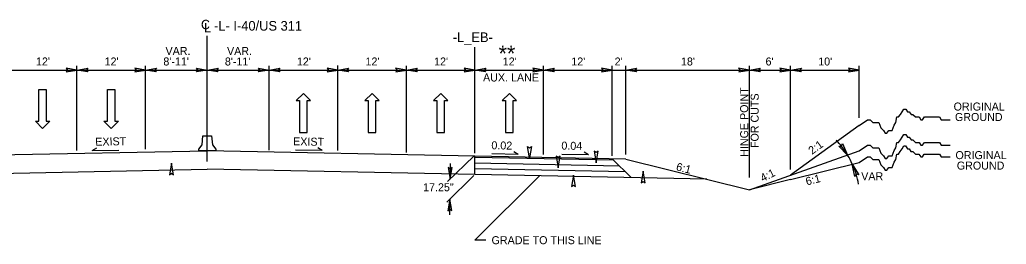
# Model space of a CAD drawing. Extents: x 1726582 to 1728895, y 538986 to 541550.
# Drawn here: x 1727397 to 1728260, y 540347 to 540544 of the extents above; entities that cross this region are included whole.
import ezdxf

# ---------------------------------------------------------------- set-up
doc = ezdxf.new("R2010")
doc.units = 0
for name, color, linetype in [('Default', 7, 'Continuous'), ('GSExisting', 7, 'Continuous'), ('GSProposed', 7, 'Continuous'), ('GSRelocate', 7, 'Continuous'), ('GSRemove', 7, 'Continuous'), ('GSReplace', 7, 'Continuous'), ('Typical Terminator CELL', 7, 'Continuous'), ('Typical Text General CELL', 7, 'Continuous')]:
    doc.layers.add(name, color=color, linetype=linetype)

msp = doc.modelspace()

# ---------------------------------------------------------------- linework, layer by layer
at = {"layer": 'Default'}
for p, q in [((1727795.33, 540427.18), (1727795.33, 540520.09)), ((1727447.04, 540429.59), (1727447.04, 540503.77)), ((1727507.09, 540430.79), (1727507.09, 540503.77)), ((1727615.18, 540429.8), (1727615.18, 540503.77)), ((1727675.34, 540429.58), (1727675.34, 540503.92)), ((1727735.39, 540427.79), (1727735.39, 540503.89)), ((1727795.33, 540427.18), (1727795.33, 540503.89)), ((1727855.37, 540425.98), (1727855.37, 540503.77)), ((1727915.42, 540425.98), (1727915.42, 540503.77)), ((1727915.42, 540424.78), (1727915.42, 540503.77)), ((1727927.43, 540425.98), (1727927.43, 540503.77)), ((1728035.55, 540405.77), (1728035.55, 540503.77)), ((1728071.58, 540412.81), (1728071.58, 540503.77)), ((1728131.63, 540458.2), (1728131.63, 540503.77)), ((1727386.99, 540500.07), (1727447.04, 540500.07)), ((1727447.04, 540500.07), (1727507.09, 540500.07)), ((1727507.09, 540500.07), (1727561.09, 540500.07)), ((1727561.09, 540500.07), (1727615.29, 540500.07)), ((1727615.29, 540500.07), (1727675.34, 540500.07)), ((1727675.34, 540500.07), (1727735.39, 540500.07)), ((1727735.39, 540500.07), (1727795.43, 540500.07)), ((1727795.43, 540500.07), (1727855.48, 540500.07)), ((1727855.48, 540500.07), (1727915.53, 540500.07)), ((1727855.48, 540500.07), (1727915.53, 540500.07)), ((1727915.53, 540500.07), (1727927.43, 540500.07)), ((1727927.43, 540500.07), (1728035.51, 540500.07)), ((1728035.51, 540500.07), (1728071.54, 540500.07)), ((1728071.54, 540500.07), (1728131.59, 540500.07)), ((1727413.62, 540455.17), (1727413.62, 540483.17)), ((1727413.62, 540483.17), (1727420.22, 540483.17)), ((1727420.22, 540483.17), (1727420.22, 540455.17)), ((1727473.66, 540455.17), (1727473.66, 540483.17)), ((1727473.66, 540483.17), (1727480.26, 540483.17)), ((1727480.26, 540483.17), (1727480.26, 540455.17)), ((1727645.32, 540479.59), (1727638.92, 540473.29)), ((1727651.52, 540473.29), (1727645.32, 540479.59)), ((1727705.36, 540479.59), (1727698.96, 540473.29)), ((1727711.56, 540473.29), (1727705.36, 540479.59)), ((1727765.41, 540479.59), (1727759.01, 540473.29)), ((1727771.61, 540473.29), (1727765.41, 540479.59)), ((1727825.46, 540479.59), (1727819.06, 540473.29)), ((1727831.66, 540473.29), (1727825.46, 540479.59)), ((1727638.92, 540473.29), (1727641.92, 540473.29)), ((1727641.92, 540473.29), (1727641.92, 540445.29)), ((1727648.52, 540445.29), (1727648.52, 540473.29)), ((1727648.52, 540473.29), (1727651.52, 540473.29)), ((1727698.96, 540473.29), (1727701.96, 540473.29)), ((1727701.96, 540473.29), (1727701.96, 540445.29)), ((1727708.56, 540445.29), (1727708.56, 540473.29)), ((1727708.56, 540473.29), (1727711.56, 540473.29)), ((1727759.01, 540473.29), (1727762.01, 540473.29)), ((1727762.01, 540473.29), (1727762.01, 540445.29)), ((1727768.61, 540445.29), (1727768.61, 540473.29)), ((1727768.61, 540473.29), (1727771.61, 540473.29)), ((1727819.06, 540473.29), (1727822.06, 540473.29)), ((1727822.06, 540473.29), (1727822.06, 540445.29)), ((1727828.66, 540445.29), (1727828.66, 540473.29)), ((1727828.66, 540473.29), (1727831.66, 540473.29)), ((1727417.02, 540448.87), (1727410.62, 540455.17)), ((1727410.62, 540455.17), (1727413.62, 540455.17)), ((1727423.22, 540455.17), (1727417.02, 540448.87)), ((1727420.22, 540455.17), (1727423.22, 540455.17)), ((1727477.06, 540448.87), (1727470.66, 540455.17)), ((1727470.66, 540455.17), (1727473.66, 540455.17)), ((1727483.26, 540455.17), (1727477.06, 540448.87)), ((1727480.26, 540455.17), (1727483.26, 540455.17)), ((1727641.92, 540445.29), (1727648.52, 540445.29)), ((1727701.96, 540445.29), (1727708.56, 540445.29)), ((1727762.01, 540445.29), (1727768.61, 540445.29)), ((1727822.06, 540445.29), (1727828.66, 540445.29)), ((1727794.5, 540424.56), (1727771.21, 540402.26)), ((1727773.55, 540418.26), (1727773.55, 540404.5)), ((1727794.5, 540407.67), (1727770.67, 540384.19)), ((1727773.43, 540373.15), (1727773.43, 540386.91))]:
    msp.add_line(p, q, dxfattribs=at)
for points in [[(1727437.66, 540498.46), (1727447.04, 540500.07), (1727437.61, 540501.74), (1727438.81, 540500.07)], [(1727456.42, 540498.46), (1727447.04, 540500.07), (1727456.47, 540501.74), (1727455.27, 540500.07)], [(1727497.71, 540498.46), (1727507.09, 540500.07), (1727497.66, 540501.74), (1727498.85, 540500.07)], [(1727516.47, 540498.46), (1727507.09, 540500.07), (1727516.52, 540501.74), (1727515.32, 540500.07)], [(1727551.71, 540501.69), (1727561.09, 540500.07), (1727551.66, 540498.41), (1727552.85, 540500.07)], [(1727570.46, 540498.45), (1727561.09, 540500.07), (1727570.52, 540501.74), (1727569.32, 540500.07)], [(1727605.81, 540501.69), (1727615.18, 540500.07), (1727605.75, 540498.4), (1727606.95, 540500.07)], [(1727624.56, 540498.45), (1727615.18, 540500.07), (1727624.61, 540501.74), (1727623.42, 540500.07)], [(1727665.96, 540498.45), (1727675.34, 540500.07), (1727665.91, 540501.74), (1727667.11, 540500.07)], [(1727684.72, 540498.45), (1727675.34, 540500.07), (1727684.77, 540501.74), (1727683.57, 540500.07)], [(1727726.01, 540498.45), (1727735.39, 540500.07), (1727725.96, 540501.74), (1727727.16, 540500.07)], [(1727744.77, 540498.45), (1727735.39, 540500.07), (1727744.82, 540501.74), (1727743.62, 540500.07)], [(1727785.95, 540498.45), (1727795.33, 540500.07), (1727785.9, 540501.74), (1727787.09, 540500.07)], [(1727804.7, 540498.45), (1727795.33, 540500.07), (1727804.76, 540501.74), (1727803.56, 540500.07)], [(1727845.99, 540498.45), (1727855.37, 540500.07), (1727845.94, 540501.74), (1727847.14, 540500.07)], [(1727864.75, 540498.45), (1727855.37, 540500.07), (1727864.8, 540501.74), (1727863.6, 540500.07)], [(1727906.04, 540498.45), (1727915.42, 540500.07), (1727905.99, 540501.74), (1727907.19, 540500.07)], [(1727936.81, 540498.45), (1727927.43, 540500.07), (1727936.86, 540501.74), (1727935.66, 540500.07)], [(1728026.17, 540498.46), (1728035.55, 540500.08), (1728026.12, 540501.74), (1728027.32, 540500.08)], [(1728044.93, 540498.46), (1728035.55, 540500.08), (1728044.98, 540501.74), (1728043.78, 540500.08)], [(1728062.2, 540498.46), (1728071.58, 540500.08), (1728062.15, 540501.74), (1728063.35, 540500.08)], [(1728080.96, 540498.46), (1728071.58, 540500.08), (1728081.01, 540501.74), (1728079.81, 540500.08)], [(1728122.21, 540498.45), (1728131.59, 540500.07), (1728122.16, 540501.74), (1728123.36, 540500.07)], [(1728116.91, 540435.57), (1728121.46, 540425.59), (1728113.75, 540433.49), (1728116.12, 540433.43)], [(1728127.83, 540406.84), (1728125.5, 540417.56), (1728131.36, 540408.2), (1728129.06, 540408.76)], [(1728127.83, 540406.84), (1728125.5, 540417.56), (1728131.36, 540408.2), (1728129.06, 540408.76)]]:
    msp.add_lwpolyline(points, close=True, dxfattribs=at)
at = {"layer": 'GSExisting'}
for points in [[(1728131.59, 540451.51), (1728138.81, 540456.57), (1728141.15, 540456.57), (1728143.48, 540454.24), (1728145.04, 540454.24), (1728147.38, 540454.24), (1728148.93, 540454.24), (1728150.49, 540449.55), (1728152.83, 540447.23), (1728154.39, 540444.88), (1728155.94, 540444.88), (1728157.5, 540447.23), (1728159.06, 540447.23), (1728160.61, 540447.23), (1728162.17, 540451.9), (1728163.73, 540454.24), (1728164.51, 540458.92), (1728166.07, 540458.92), (1728167.63, 540461.24), (1728169.18, 540463.59), (1728170.74, 540465.93), (1728172.3, 540465.93), (1728173.85, 540463.59), (1728175.41, 540463.59), (1728176.97, 540461.24), (1728178.53, 540461.24), (1728180.87, 540458.92), (1728182.42, 540458.92), (1728183.98, 540458.92), (1728185.54, 540456.57), (1728187.09, 540456.57), (1728188.65, 540458.92), (1728190.21, 540458.92), (1728191.77, 540458.92), (1728193.32, 540458.92), (1728194.88, 540458.92), (1728197.22, 540458.92), (1728199.55, 540458.92), (1728201.89, 540458.92), (1728203.45, 540456.57), (1728205.78, 540456.57), (1728208.12, 540456.57), (1728211.23, 540456.57)], [(1728131.59, 540429.19), (1728138.81, 540434.26), (1728141.15, 540434.26), (1728143.48, 540431.93), (1728145.04, 540431.93), (1728147.38, 540431.93), (1728148.93, 540431.93), (1728150.49, 540427.24), (1728152.83, 540424.92), (1728154.39, 540422.57), (1728155.94, 540422.57), (1728157.5, 540424.92), (1728159.06, 540424.92), (1728160.61, 540424.92), (1728162.17, 540429.59), (1728163.73, 540431.93), (1728164.51, 540436.6), (1728166.07, 540436.6), (1728167.63, 540438.93), (1728169.18, 540441.28), (1728170.74, 540443.62), (1728172.3, 540443.62), (1728173.85, 540441.28), (1728175.41, 540441.28), (1728176.97, 540438.93), (1728178.53, 540438.93), (1728180.87, 540436.6), (1728182.42, 540436.6), (1728183.98, 540436.6), (1728185.54, 540434.26), (1728187.09, 540434.26), (1728188.65, 540436.6), (1728190.21, 540436.6), (1728191.77, 540436.6), (1728193.32, 540436.6), (1728194.88, 540436.6), (1728197.22, 540436.6), (1728199.55, 540436.6), (1728201.89, 540436.6), (1728203.45, 540434.26), (1728205.78, 540434.26), (1728208.12, 540434.26), (1728211.23, 540434.26)], [(1728131.56, 540419.07), (1728138.77, 540424.14), (1728141.11, 540424.14), (1728143.45, 540421.81), (1728145, 540421.81), (1728147.34, 540421.81), (1728148.9, 540421.81), (1728150.46, 540417.12), (1728152.8, 540414.79), (1728154.35, 540412.45), (1728155.91, 540412.45), (1728157.47, 540414.79), (1728159.03, 540414.79), (1728160.58, 540414.79), (1728162.14, 540419.46), (1728163.7, 540421.81), (1728164.48, 540426.48), (1728166.04, 540426.48), (1728167.59, 540428.81), (1728169.15, 540431.15), (1728170.71, 540433.5), (1728172.26, 540433.5), (1728173.82, 540431.15), (1728175.38, 540431.15), (1728176.94, 540428.81), (1728178.49, 540428.81), (1728180.83, 540426.48), (1728182.39, 540426.48), (1728183.95, 540426.48), (1728185.5, 540424.14), (1728187.06, 540424.14), (1728188.62, 540426.48), (1728190.18, 540426.48), (1728191.73, 540426.48), (1728193.29, 540426.48), (1728194.85, 540426.48), (1728197.19, 540426.48), (1728199.52, 540426.48), (1728201.86, 540426.48), (1728203.42, 540424.14), (1728205.75, 540424.14), (1728208.09, 540424.14), (1728211.2, 540424.14)]]:
    msp.add_lwpolyline(points, dxfattribs=at)
for centre, start, end in [((1728069.06, 540395.64), 29.75191, 45.50364), ((1728071.52, 540390.56), 8.9538, 26.57006), ((1728071.52, 540390.56), 8.9538, 26.57006)]:
    msp.add_arc(centre, 60.35, start, end, dxfattribs=at)
msp.add_ellipse((1728070.97, 540428.62), major_axis=(54.47, -25.99), ratio=0.5, start_param=0.463735, end_param=0.681536, dxfattribs=at)
at = {"layer": 'GSProposed'}
for p, q in [((1727460.45, 540429.46), (1727464.36, 540431.83)), ((1727460.45, 540429.46), (1727483.76, 540429.93)), ((1727661.73, 540429.46), (1727638.41, 540429.93)), ((1727661.73, 540429.46), (1727657.81, 540431.83)), ((1727833.3, 540426.03), (1727809.99, 540426.5)), ((1727833.3, 540426.03), (1727829.38, 540428.4)), ((1727894.75, 540425.72), (1727871.44, 540426.19)), ((1727894.75, 540425.72), (1727890.84, 540428.09))]:
    msp.add_line(p, q, dxfattribs=at)
at = {"layer": 'GSRemove'}
msp.add_line((1727561.09, 540419.94), (1727561.09, 540530.03), dxfattribs=at)
at = {"layer": 'GSReplace'}
for p, q in [((1728131.59, 540451.51), (1728071.62, 540407.89)), ((1727553.59, 540430.63), (1727556.5, 540434.5)), ((1727556.5, 540434.5), (1727557.33, 540442.42)), ((1727557.33, 540442.42), (1727561.09, 540442.42)), ((1727561.09, 540442.42), (1727564.84, 540442.42)), ((1727564.84, 540442.42), (1727565.67, 540434.5)), ((1727565.67, 540434.5), (1727568.58, 540430.63)), ((1727326.84, 540424.71), (1727561.06, 540429.4)), ((1727553.59, 540429.38), (1727553.59, 540430.63)), ((1727568.58, 540429.38), (1727553.59, 540429.38)), ((1727795.33, 540424.71), (1727561.09, 540429.4)), ((1727568.58, 540430.63), (1727568.58, 540429.38)), ((1728035.5, 540395.05), (1728131.59, 540429.19)), ((1727795.33, 540408.45), (1727795.33, 540424.71)), ((1727927.44, 540422.07), (1727795.33, 540424.71)), ((1727916.7, 540421.05), (1727795.33, 540423.48)), ((1727921.83, 540415.93), (1727795.33, 540418.46)), ((1727915.42, 540422.33), (1727932.01, 540405.74)), ((1727927.44, 540422.07), (1728035.51, 540395.05)), ((1728071.52, 540404.06), (1728131.56, 540419.07)), ((1727326.84, 540408.45), (1727561.09, 540413.13)), ((1727795.33, 540408.45), (1727561.09, 540413.13)), ((1727926.93, 540410.82), (1727795.33, 540413.45)), ((1727998.15, 540404.39), (1727795.33, 540408.45)), ((1728071.52, 540404.06), (1728035.5, 540395.05))]:
    msp.add_line(p, q, dxfattribs=at)
at = {"layer": 'Typical Terminator CELL'}
for p, q in [((1727795.32, 540350.93), (1727851.78, 540407.32)), ((1727804.88, 540350.93), (1727795.32, 540350.93))]:
    msp.add_line(p, q, dxfattribs=at)
for points in [[(1727844.91, 540433.1), (1727843.18, 540423.05), (1727841.39, 540433.15), (1727843.18, 540431.87)], [(1727899.78, 540428.89), (1727901.51, 540418.85), (1727903.29, 540428.95), (1727901.51, 540427.66)], [(1727531.5, 540408.34), (1727529.77, 540418.38), (1727527.98, 540408.28), (1727529.77, 540409.56)], [(1727866.52, 540424.5), (1727868.25, 540414.46), (1727870.03, 540424.56), (1727868.25, 540423.28)], [(1727771.82, 540414.55), (1727773.55, 540404.5), (1727775.33, 540414.61), (1727773.55, 540413.32)], [(1727883.38, 540397.96), (1727881.65, 540408.01), (1727879.86, 540397.91), (1727881.65, 540399.19)], [(1727944.38, 540401.3), (1727942.65, 540411.34), (1727940.86, 540401.24), (1727942.65, 540402.52)], [(1727775.16, 540376.86), (1727773.43, 540386.91), (1727771.64, 540376.81), (1727773.43, 540378.09)]]:
    msp.add_lwpolyline(points, close=True, dxfattribs=at)

# ---------------------------------------------------------------- texts
at = {"layer": 'Default'}
msp.add_text('17.25"', height=7.005, rotation=360, dxfattribs=at).set_placement((1727749.98, 540393.86))
at = {"layer": 'GSProposed'}
for s, height, p in [('VAR.', 7.005, (1727524.54, 540513.26)), ('VAR.', 7.005, (1727578.37, 540513.26)), ('**', 14.011, (1727816.07, 540507.58)), ("12'", 7.005, (1727411.2, 540504.08)), ("12'", 7.005, (1727471.25, 540504.08)), ("8'-11'", 7.005, (1727522.66, 540504.08)), ("8'-11'", 7.005, (1727576.49, 540504.07)), ("12'", 7.005, (1727639.5, 540504.07)), ("12'", 7.005, (1727699.55, 540504.07)), ("12'", 7.005, (1727759.6, 540504.07)), ("12'", 7.005, (1727819.65, 540504.07)), ("12'", 7.005, (1727879.69, 540504.07)), ("2'", 7.005, (1727917.6, 540504.07)), ('AUX. LANE', 7.005, (1727802.43, 540490.06))]:
    msp.add_text(s, height=height, dxfattribs=at).set_placement(p)
for s, rotation, p in [('EXIST', 1.14574, (1727463.13, 540433.69)), ('EXIST', 358.85426, (1727636.19, 540434.15)), ('0.02', 358.85426, (1727809.67, 540430.68)), ('0.04', 358.85426, (1727870.93, 540430.38))]:
    msp.add_text(s, height=7.005, rotation=rotation, dxfattribs=at).set_placement(p)
at = {"layer": 'GSRelocate'}
for s, p in [("18'", (1727975.66, 540504.07)), ("6'", (1728049.65, 540504.07)), ("10'", (1728095.75, 540504.07)), ('ORIGINAL', (1728214.25, 540464.59)), ('GROUND', (1728215.43, 540455.41)), ('ORIGINAL', (1728215.87, 540422)), ('GROUND', (1728217.05, 540412.82)), ('VAR', (1728133.39, 540403.45))]:
    msp.add_text(s, height=7.005, dxfattribs=at).set_placement(p)
for s, height, rotation, p in [('HINGE POINT', 7.0055, 90, (1728034.46, 540424.05)), ('FOR CUTS', 7.005, 90, (1728043.65, 540431.72)), ('2:1', 7.005, 36.02984, (1728090.3, 540425.68)), ('6:1', 7.005, 345.96376, (1727970.91, 540412.26)), ('4:1', 7.005, 26.57006, (1728047.22, 540401.84)), ('6:1', 7.005, 14.03809, (1728085.73, 540398.9))]:
    msp.add_text(s, height=height, rotation=rotation, dxfattribs=at).set_placement(p)
at = {"layer": 'GSRemove'}
for s, height, rotation, p in [('C', 8.2, 0.04425, (1727555.56, 540535.88)), ('L', 8.21, 359.99115, (1727558.29, 540533.08)), ('-L- I-40/US 311', 8.4214, 359.94168, (1727567.06, 540534.69))]:
    msp.add_text(s, height=height, rotation=rotation, dxfattribs=at).set_placement(p)
msp.add_text('-L_EB-', height=8.421, dxfattribs=at).set_placement((1727775.96, 540524.63))
at = {"layer": 'Typical Text General CELL'}
msp.add_text('GRADE TO THIS LINE', height=7.0055, rotation=360, dxfattribs=at).set_placement((1727809.88, 540347.43))

doc.saveas('drawing.dxf')
